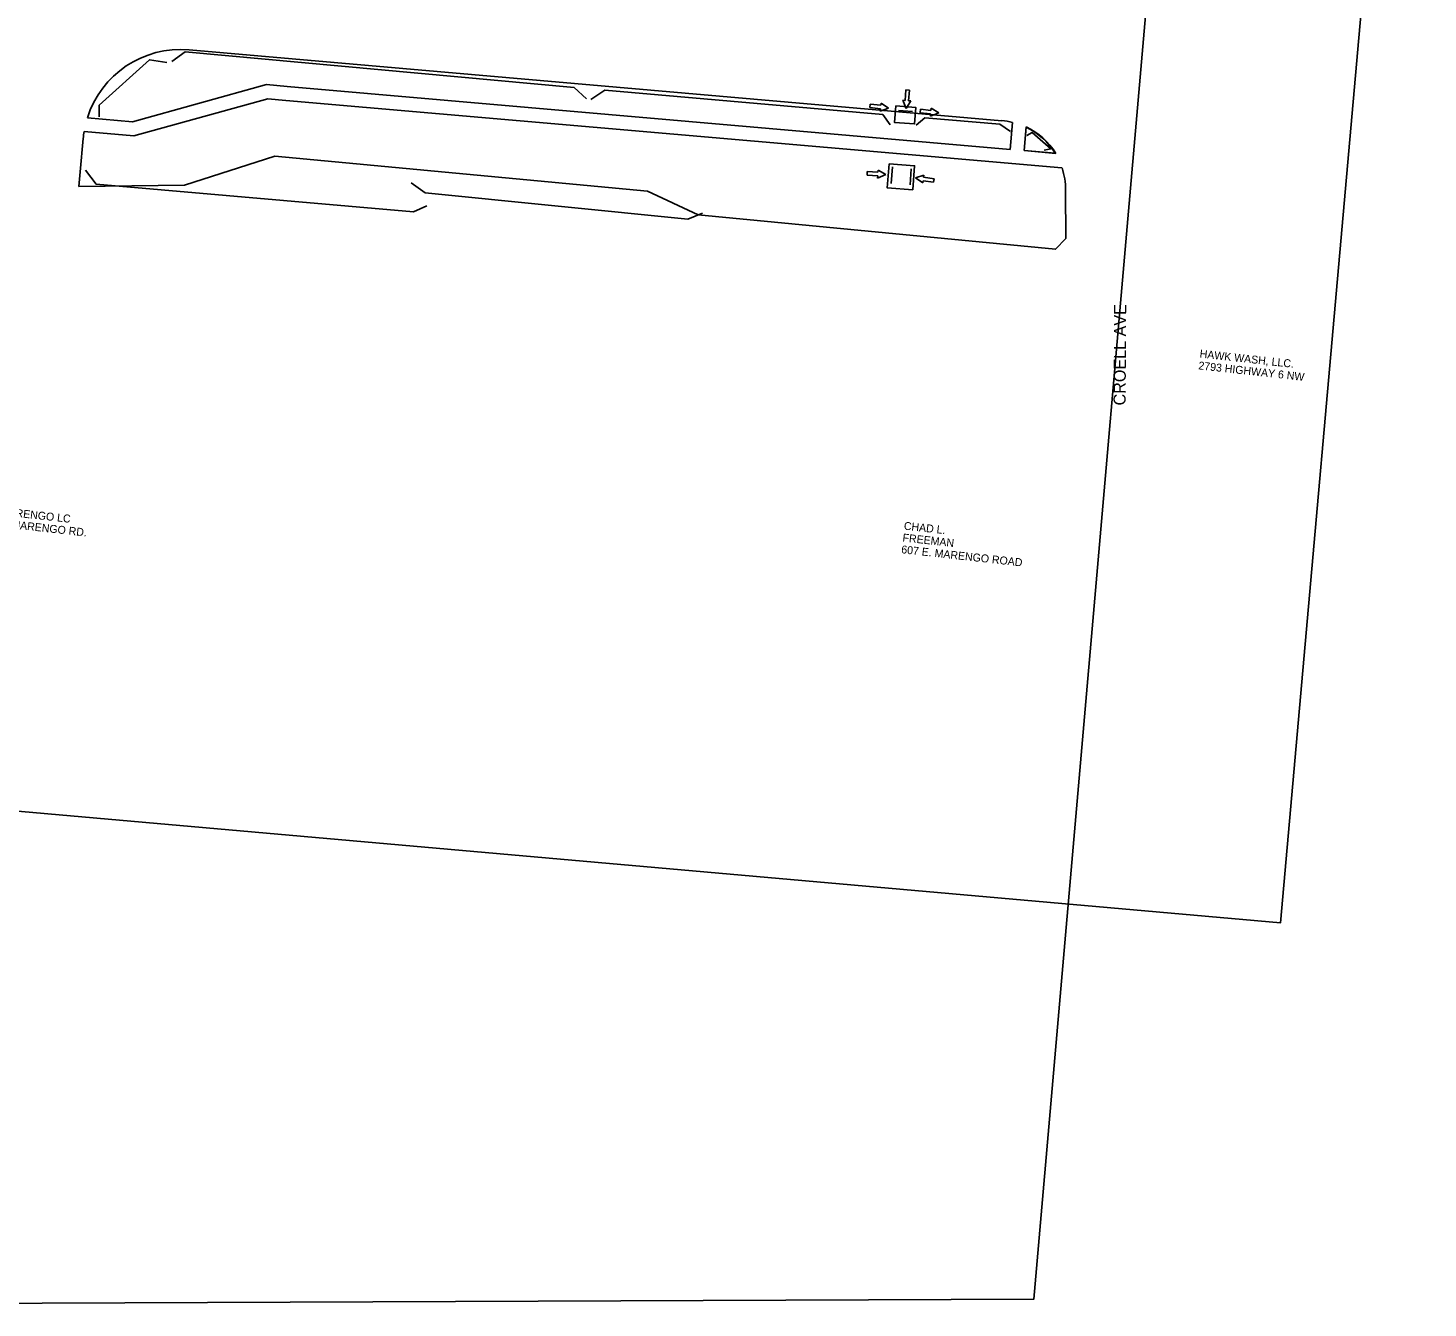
# Model space of a CAD drawing. Extents: x 20499990 to 20504504, y 7953381 to 7954379.
# Drawn here: x 20502160 to 20502661, y 7953381 to 7953839 of the extents above; entities that cross this region are included whole.
import ezdxf

# ---------------------------------------------------------------- set-up
doc = ezdxf.new("R2010")
doc.units = 0
for name, color, linetype in [('Draft_DNC', 7, 'Continuous'), ('dsnCellElements', 7, 'Continuous'), ('ErosionControl', 7, 'Continuous'), ('NamedBoundary', 7, 'Continuous'), ('rowdsnSymbolsProposed', 7, 'Continuous'), ('Seeding', 7, 'Continuous'), ('Text', 7, 'Continuous')]:
    doc.layers.add(name, color=color, linetype=linetype)

msp = doc.modelspace()

# ---------------------------------------------------------------- linework, layer by layer
at = {"layer": 'Draft_DNC'}
msp.add_lwpolyline([(20501839.61, 7954376.08), (20501750.51, 7953380.96), (20502519.96, 7953384.14), (20502606.52, 7954378.84)], close=True, dxfattribs=at)
at = {"layer": 'dsnCellElements'}
for p, q in [((20502473.84, 7953813.4), (20502474.16, 7953817.2)), ((20502474.16, 7953817.2), (20502475.42, 7953817.1)), ((20502475.42, 7953817.1), (20502475.11, 7953813.29)), ((20502461.24, 7953810.87), (20502461.4, 7953812.14)), ((20502465.03, 7953810.42), (20502461.24, 7953810.87)), ((20502461.4, 7953812.14), (20502465.18, 7953811.68)), ((20502467.95, 7953810.71), (20502464.94, 7953809.63)), ((20502465.18, 7953811.68), (20502465.28, 7953812.47)), ((20502465.28, 7953812.47), (20502467.95, 7953810.71)), ((20502474.24, 7953810.49), (20502473.05, 7953813.47)), ((20502473.05, 7953813.47), (20502473.84, 7953813.4)), ((20502475.9, 7953813.23), (20502474.24, 7953810.49)), ((20502475.11, 7953813.29), (20502475.9, 7953813.23)), ((20502483.13, 7953809.88), (20502483.22, 7953810.67)), ((20502483.22, 7953810.67), (20502485.91, 7953808.94)), ((20502464.94, 7953809.63), (20502465.03, 7953810.42)), ((20502479.2, 7953809.04), (20502479.34, 7953810.3)), ((20502483, 7953808.62), (20502479.2, 7953809.04)), ((20502479.34, 7953810.3), (20502483.13, 7953809.88)), ((20502485.91, 7953808.94), (20502482.91, 7953807.83)), ((20502482.91, 7953807.83), (20502483, 7953808.62)), ((20502460.24, 7953786.7), (20502460.33, 7953787.97)), ((20502464.05, 7953786.43), (20502460.24, 7953786.7)), ((20502460.33, 7953787.97), (20502464.14, 7953787.7)), ((20502466.95, 7953786.87), (20502463.99, 7953785.64)), ((20502463.99, 7953785.64), (20502464.05, 7953786.43)), ((20502464.14, 7953787.7), (20502464.19, 7953788.5)), ((20502464.19, 7953788.5), (20502466.95, 7953786.87)), ((20502477.55, 7953785.69), (20502480.58, 7953786.71)), ((20502480.18, 7953783.87), (20502477.55, 7953785.69)), ((20502480.58, 7953786.71), (20502480.47, 7953785.92)), ((20502480.47, 7953785.92), (20502484.25, 7953785.39)), ((20502480.29, 7953784.66), (20502480.18, 7953783.87)), ((20502484.07, 7953784.13), (20502480.29, 7953784.66)), ((20502484.25, 7953785.39), (20502484.07, 7953784.13))]:
    msp.add_line(p, q, dxfattribs=at)
at = {"layer": 'ErosionControl'}
for p, q in [((20502471.52, 7953809.87), (20502476.5, 7953809.48)), ((20502516.46, 7953795.45), (20502517.21, 7953803.97)), ((20502527.83, 7953794.46), (20502516.46, 7953795.45)), ((20502468.91, 7953783.66), (20502469.4, 7953789.6)), ((20502476.04, 7953788.97), (20502475.68, 7953783.18))]:
    msp.add_line(p, q, dxfattribs=at)
for points in [[(20502359.81, 7953814), (20502355.35, 7953818.09), (20502216.09, 7953830.78), (20502211.33, 7953827.35)], [(20502185.24, 7953807.56), (20502185.31, 7953811.7), (20502203.26, 7953828.02), (20502209.53, 7953827.04)], [(20502468.48, 7953804.71), (20502465.88, 7953808.42), (20502366.31, 7953817.16), (20502361.29, 7953813.81)], [(20502477.86, 7953804.6), (20502480.9, 7953807.15), (20502507.74, 7953804.96), (20502511.58, 7953802.28)], [(20502517.5, 7953800.92), (20502519.42, 7953801.94), (20502526.09, 7953796.07), (20502523.71, 7953795.62)], [(20502180.41, 7953788.49), (20502184.13, 7953783.44), (20502297.82, 7953773.48), (20502302.57, 7953775.71)], [(20502296.93, 7953783.88), (20502301.98, 7953780.32), (20502396.06, 7953770.95), (20502401.26, 7953773.03)]]:
    msp.add_lwpolyline(points, dxfattribs=at)
for points in [[(20502470.5, 7953811.45), (20502477.72, 7953810.88), (20502477.26, 7953804.99), (20502470.03, 7953805.56)], [(20502468.1, 7953790.75), (20502477.26, 7953790.02), (20502476.58, 7953781.41), (20502467.41, 7953782.14)]]:
    msp.add_lwpolyline(points, close=True, dxfattribs=at)
msp.add_arc((20502506.97, 7953781.85), 24.37, 31.16, 65.1805, dxfattribs=at)
at = {"layer": 'NamedBoundary'}
msp.add_lwpolyline([(20501724.26, 7954199.37), (20501671.43, 7953601.7), (20502608.28, 7953518.89), (20502661.11, 7954116.56)], close=True, dxfattribs=at)
at = {"layer": 'rowdsnSymbolsProposed'}
for p, q in [((20502508.52, 7953806.18), (20502217.45, 7953831.54)), ((20502252.58, 7953818.44), (20502511.48, 7953795.89)), ((20502252.15, 7953813.46), (20502530.04, 7953789.25)), ((20502511.48, 7953795.89), (20502512.33, 7953805.55)), ((20502516.46, 7953795.45), (20502517.19, 7953803.81)), ((20502178.48, 7953787.8), (20502179.55, 7953799.79)), ((20502527.58, 7953794.49), (20502516.46, 7953795.45)), ((20502178.01, 7953782.62), (20502178.48, 7953787.8)), ((20502531.35, 7953781.31), (20502531.37, 7953763.95))]:
    msp.add_line(p, q, dxfattribs=at)
for points in [[(20502181.04, 7953807.25), (20502197.25, 7953805.8), (20502245.18, 7953819.09), (20502252.58, 7953818.44)], [(20502179.87, 7953802.33), (20502197.71, 7953800.73), (20502245.65, 7953814.03), (20502252.15, 7953813.46)], [(20502531.37, 7953763.95), (20502527.77, 7953760.12), (20502399.74, 7953772.45), (20502381.6, 7953780.92), (20502248.13, 7953793.49), (20502215.79, 7953783.03), (20502178.01, 7953782.62)]]:
    msp.add_lwpolyline(points, dxfattribs=at)
for centre, radius, start, end in [((20502214.41, 7953796.67), 35, 85.0212, 162.4173), ((20502506.35, 7953781.28), 25, 76.1735, 85.0212), ((20502214.41, 7953796.67), 35, 170.6968, 174.8834), ((20502506.35, 7953781.28), 25, 31.8911, 64.3008), ((20502506.35, 7953781.28), 25, 0.0729, 18.5994)]:
    msp.add_arc(centre, radius, start, end, dxfattribs=at)
at = {"layer": 'Seeding'}
for p, q in [((20502508.52, 7953806.18), (20502217.45, 7953831.54)), ((20502252.58, 7953818.44), (20502511.48, 7953795.89)), ((20502252.15, 7953813.46), (20502530.04, 7953789.25)), ((20502511.48, 7953795.89), (20502512.33, 7953805.55)), ((20502516.46, 7953795.45), (20502517.19, 7953803.81)), ((20502178.48, 7953787.8), (20502179.55, 7953799.79)), ((20502527.58, 7953794.49), (20502516.46, 7953795.45)), ((20502178.01, 7953782.62), (20502178.48, 7953787.8)), ((20502531.35, 7953781.31), (20502531.37, 7953763.95))]:
    msp.add_line(p, q, dxfattribs=at)
for points in [[(20502181.04, 7953807.25), (20502197.25, 7953805.8), (20502245.18, 7953819.09), (20502252.58, 7953818.44)], [(20502179.87, 7953802.33), (20502197.71, 7953800.73), (20502245.65, 7953814.03), (20502252.15, 7953813.46)], [(20502531.37, 7953763.95), (20502527.77, 7953760.12), (20502399.74, 7953772.45), (20502381.6, 7953780.92), (20502248.13, 7953793.49), (20502215.79, 7953783.03), (20502178.01, 7953782.62)]]:
    msp.add_lwpolyline(points, dxfattribs=at)
for centre, radius, start, end in [((20502214.41, 7953796.67), 35, 85.0212, 162.4173), ((20502506.35, 7953781.28), 25, 76.1735, 85.0212), ((20502214.41, 7953796.67), 35, 170.6968, 174.8834), ((20502506.35, 7953781.28), 25, 31.8911, 64.3008), ((20502506.35, 7953781.28), 25, 0.0729, 18.5994)]:
    msp.add_arc(centre, radius, start, end, dxfattribs=at)

# ---------------------------------------------------------------- texts
at = {"layer": 'Text'}
for s, height, rotation, p in [('CROELL AVE', 4.32, 89.6519, (20502552.82, 7953704.18)), ('HAWK WASH, LLC.', 2.8346, 353.7082, (20502579.23, 7953721.37)), ('2793 HIGHWAY 6 NW', 2.8346, 353.7082, (20502578.77, 7953717.14)), ('443 MARENGO LC', 2.8346, 353.7082, (20502142.21, 7953665.76)), ('443 E. MARENGO RD.', 2.8346, 353.7082, (20502141.75, 7953661.54)), ('CHAD L.', 2.835, 353.7082, (20502473.3, 7953659.74)), ('FREEMAN', 2.835, 353.7082, (20502472.83, 7953655.51)), ('607 E. MARENGO ROAD', 2.8346, 353.7082, (20502472.37, 7953651.29))]:
    msp.add_text(s, height=height, rotation=rotation, dxfattribs=at).set_placement(p)

doc.saveas('drawing.dxf')
